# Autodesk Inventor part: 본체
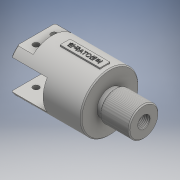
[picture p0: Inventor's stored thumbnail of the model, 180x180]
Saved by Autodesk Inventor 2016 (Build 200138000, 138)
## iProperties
Created: 2019-02
Part Number: 본체
Material: 일반
Document SubType Name: Modeling
Designer: 605-12
Density: 1 g/cm^3
Appearance: 기본값
Author: 605-12
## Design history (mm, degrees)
sketch "스케치1"
  geometry: L1 (0, 0)-(0, 29); L2 (0, 29)-(38, 29); L3 (38, 29)-(38, 13); L4 (38, 13)-(43, 13); L5 (43, 13)-(43, 15); L6 (43, 15)-(72, 15); L7 (72, 15)-(72, 0); L8 (72, 0)-(0, 0); L9 (0, 14)-(2.65, 14); L10 (2.65, 14)-(2.65, 16.2); L11 (3.45, 17)-(6.55, 17); L12 (7.35, 16.2)-(7.35, 14); L13 (7.35, 14)-(11.65, 14); L14 (11.65, 14)-(11.65, 16.2); L15 (12.45, 17)-(15.55, 17); L16 (16.35, 16.2)-(16.35, 14); L17 (16.35, 14)-(20, 14); L18 (20, 14)-(20, 16); L19 (20, 16)-(27, 16); L20 (27, 16)-(27, 4); L21 (27, 4)-(72, 4); A1 r 0.8 centre (3.45, 16.2) between (3.45, 17) and (2.65, 16.2); A2 r 0.8 centre (6.55, 16.2) between (7.35, 16.2) and (6.55, 17); A3 r 0.8 centre (12.45, 16.2) between (12.45, 17) and (11.65, 16.2); A4 r 0.8 centre (15.55, 16.2) between (16.35, 16.2) and (15.55, 17); 2 further points
  constraints: 42 end point, 18 perpendicular, 8 point on circle, 8 tangent, 7 point on line, 4 centre point, 3 equal radius, 2 horizontal, 1 vertical
  dimensions: "d21" = 72 distance between parallel lines of L7 L1; "d22" = 26 diameter of L4 L8; "d23" = 5 distance between parallel lines of L5 L3; "d24" = 30 diameter of L6 L8; "d25" = 58 diameter of L2 L8; "d26" = 34 distance between parallel lines of L7 L3; "d27" = 8 diameter of L21 L8; "d28" = 27 distance between parallel lines of L20 L1; "d29" = 7 distance of L18.end L19.end; "d30" = 2.65 distance between parallel lines of L10 L1; "d31" = 28 diameter of L9 L8; "d32" = 34 diameter of L11 L8; "d33" = 28 diameter of L13 L8; "d34" = 28 diameter of L17 L8; "d35" = 7.35 distance between parallel lines of L12 L1; "d36" = 3.65 distance between parallel lines of L16 L18; "d37" = 32 diameter of L19 L8; "d38" = 4.7 distance of point (11.65, 17) point (16.35, 17); "d39" = 0.8 radius of A1
revolve "회전1" sketch "스케치1" stored, may be unused: angle "d40" = 90 deg
sketch "스케치2"
  geometry: L1 (0, 0)-(-36, 0); L2 (-36, 0)-(-36, 29); L3 (-36, 29)-(0, 29); L4 (0, 29)-(0, 0)
  constraints: 8 end point, 2 parallel, 1 horizontal, 1 perpendicular
  dimensions: "d41" = 36 distance of L2.end L3.end; "d42" = 58 diameter of L3 L1
revolve "회전2" sketch "스케치2" stored, may be unused: angle "d43" = 90 deg
node "작업 평면1"
sketch "스케치3"
  geometry: L1 (0, -15)-(44, -15); L2 (44, -15)-(44, 15); L3 (44, 15)-(0, 15); L4 (0, 15)-(0, -15); L5 (36, -29)-(-38, -29) reference; L6 (20, -29)-(40, -29); L7 (40, -29)-(40, -22); L8 (40, -22)-(20, -22); L9 (20, -22)-(20, -29); L10 (36, 29)-(-38, 29) reference; L11 (20, 29)-(40, 29); L12 (40, 29)-(40, 22); L13 (40, 22)-(20, 22); L14 (20, 22)-(20, 29); 2 further points
  constraints: 24 end point, 6 parallel, 4 point on line, 3 horizontal, 3 perpendicular, 1 coincident, 1 midpoint
  dimensions: "d45" = 30 distance of L1.end L2.end; "d47" = 0 distance of point (0, 0) point (0, 0); "d48" = 44 distance of L2.end L3.end; "d49" = 7 distance of L6.end L7.end; "d50" = 7 distance of L11.end L12.end; "d51" = 20 distance from line of point (0, 0) L9; "d52" = 40 distance from line of point (0, 0) L12
extrude "돌출1" cut sketch "스케치3" stored distance "d53" = 10; taper "d54" = 0 deg
node "작업 평면2"
sketch "스케치5"
  geometry: L1 (-36, 24.819)-(-36, -24.819) reference; C1 r 3 at (-27, 9); C2 r 3 at (-27, -9); 1 further point
  constraints: 2 centre point
  dimensions: "d58" = 6 diameter of C1; "d59" = 6 diameter of C2; "d60" = 9 distance from line of L1 C2.centre; "d61" = 9 distance from line of L1 C1.centre; "d62" = 9 vertical distance of point (0, 0) C2.centre; "d63" = 9 vertical distance of point (0, 0) C1.centre
extrude "돌출2" cut sketch "스케치5" stored distance "d64" = 10; taper "d65" = 0 deg
hole "구멍1" diameter "d68" = 12.376; stored, may be unused: countersink angle "d72" = 90 deg, drill point angle "d74" = 118 deg; dims "d66" = 10, "d67" = 10, "d69" = 18, "d70" = 4, "d71" = 2, "d73" = 22
feature "스레드1" dims "d75" = 10, "d76" = 0
node "작업 평면3"
sketch "스케치6"
  geometry: L1 (-7, 5)-(33, 5); L2 (33, 5)-(33, -5); L3 (33, -5)-(-7, -5); L4 (-7, -5)-(-7, 5); L5 (38, -29)-(38, 29) reference; 2 further points
  constraints: 8 end point, 2 parallel, 1 horizontal, 1 horizontal alignment, 1 midpoint, 1 perpendicular
  dimensions: "d78" = 10 distance of L1.end L2.end; "d79" = 40 distance of L1.start L1.end; "d81" = 5 distance between parallel lines of L5 L2
extrude "돌출3" join sketch "스케치6" stored distance "d82" = 10; taper "d83" = 0 deg
sketch "스케치8"
  geometry: L1 (-7, -5)-(-7, 5) reference; L2 (33, -5)-(-7, -5) reference; 2 further points
  constraints: 1 other
  dimensions: "d86" = 20 distance from line of L1 point (13, 0); "d87" = 5 distance from line of L2 point (13, 0)
feature "엠보싱1" sketch "스케치8" dims "d39" = 0.8, "d88" = 0.5, "d89" = 0
chamfer "모따기1" distance "d90" = 1; stored, may be unused: second distance "d91" = 2, angle "d92" = 45 deg
node "솔리드1"
other parameters: "d44" = 29, "d57" = 22
